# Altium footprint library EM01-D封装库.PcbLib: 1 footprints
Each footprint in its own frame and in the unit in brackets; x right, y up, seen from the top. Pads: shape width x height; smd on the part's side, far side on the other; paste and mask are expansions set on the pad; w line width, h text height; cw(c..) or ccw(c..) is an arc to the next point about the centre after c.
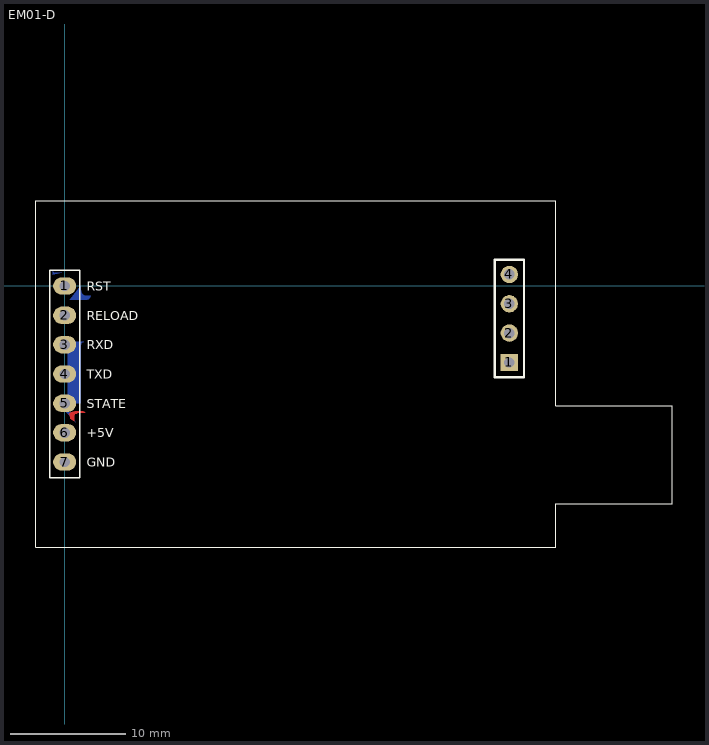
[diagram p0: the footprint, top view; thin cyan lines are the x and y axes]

## EM01-D [mm]
pads (11):
  oval 2x1.5 hole 0.9: 1(0,0) 2(0,-2.54) 3(0,-5.08) 4(0,-7.62) 5(0,-10.16) 6(0,-12.7) 7(0,-15.24)
  rect 1.5x1.5 hole 0.9: 1(38.5,-6.62)
  round 1.5 hole 0.9: 2(38.5,-4.08) 3(38.5,-1.54) 4(38.5,1)
Top Layer:
  pour cut-out: 0.83,-11.731 0.83,-11.265 0.834,-11.222 0.867,-11.143 0.928,-11.082 1.007,-11.049 1.05,-11.045 1.066,-11.03 1.102,-11.006 1.142,-10.99 1.185,-10.981 1.206,-10.98 1.787,-10.98 1.755,-10.948 1.679,-10.898 1.595,-10.863 1.506,-10.845 1.461,-10.845 0.954,-10.845 0.87,-10.845 0.705,-10.878 0.549,-10.942 0.409,-11.036 0.35,-11.095 0.378,-11.126 0.425,-11.196 0.457,-11.273 0.473,-11.355 0.475,-11.397 0.475,-11.506
Bottom Layer:
  pour cut-out: 0.956,-11.792 0.862,-11.698 0.843,-11.677 0.81,-11.628 0.788,-11.574 0.776,-11.517 0.775,-11.488 0.775,-11.339 0.776,-11.315 0.786,-11.267 0.804,-11.223 0.831,-11.182 0.847,-11.165 0.783,-11.1 0.632,-11 0.465,-10.93 0.287,-10.895 0.197,-10.895 0.075,-10.895
  pour cut-out: 1.41,-10.16 1.41,-5.087 1.415,-5.04 1.45,-4.954 1.516,-4.889 1.602,-4.853 1.649,-4.848 0.747,-4.848 0.648,-4.848 0.465,-4.924 0.326,-5.064 0.25,-5.246 0.25,-5.345 0.25,-9.935 0.25,-9.98 0.284,-10.062 0.348,-10.126 0.43,-10.16 0.475,-10.16
  pour cut-out: 1.41,0 1.41,-0.344 1.419,-0.439 1.493,-0.616 1.628,-0.751 1.804,-0.824 1.9,-0.834 2.239,-0.834 2.239,-0.906 2.184,-1.038 2.082,-1.14 1.949,-1.195 1.877,-1.195 0.419,-1.195
  pour cut-out: -0.25,1.16 -0.854,1.16 -0.891,1.164 -0.958,1.191 -1.01,1.243 -1.038,1.31 -1.041,1.347 -1.041,0.986
Top Overlay:
  lines w0.1: -2.5,-22.62 42.5,-22.62 42.5,-18.87 52.6,-18.87 52.6,-10.37 42.5,-10.37 42.5,7.38 -2.5,7.38 -2.5,-22.62
  lines w0.127: -1.3,-16.62 -1.3,1.38 1.3,1.38 1.3,-16.62 -1.3,-16.62
  lines w0.203: 37.23,-7.89 39.77,-7.89 39.77,2.27 37.23,2.27 37.23,-7.89
  text "GND" at 1.929,-15.651 h0.8
  text "+5V" at 1.929,-13.111 h0.8
  text "STATE" at 1.929,-10.571 h0.8
  text "TXD" at 1.929,-8.031 h0.8
  text "RXD" at 1.929,-5.491 h0.8
  text "RELOAD" at 1.929,-2.951 h0.8
  text "RST" at 1.929,-0.411 h0.8
3D body "SIP4.step": height 8.3, standoff -3, extent 37.23,-7.895 39.77,2.275
3D body "SIP7.step": height 8.3, standoff -3, extent -1.27,-16.515 1.27,1.275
